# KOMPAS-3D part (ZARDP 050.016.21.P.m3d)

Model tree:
1. Плоскость XY
2. Плоскость ZX
3. Плоскость ZY
4. Ось X
5. Ось Y
6. Ось Z
7. Начало координат
8. Булева операция:6
9. Булева операция:7
10. Булева операция:8
11. Булева операция:9
12. Булева операция:10
13. Булева операция:11
14. Булева операция:12
15. Булева операция:13
16. Булева операция:14  (labels: C:\Program Files\ASCON\KOMPAS-3D V13\Sys\graphic.lyt)
